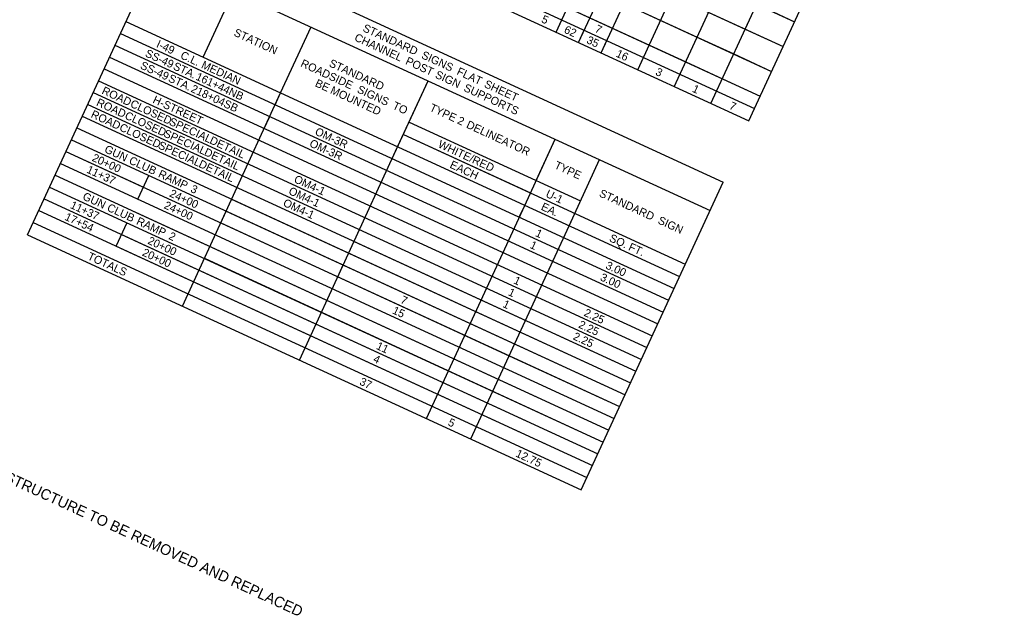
# Model space of a CAD drawing. Extents: x 627405 to 651306, y 367647 to 373471.
# Drawn here: x 650493 to 651042, y 372520 to 372856 of the extents above; entities that cross this region are included whole.
import ezdxf

# ---------------------------------------------------------------- set-up
doc = ezdxf.new("R2010")
doc.units = 0
doc.layers.add('Default', color=7, linetype='Continuous')
doc.layers.add('R_Dimension', color=7, linetype='Continuous')

msp = doc.modelspace()

# ---------------------------------------------------------------- linework, layer by layer
at = {"layer": 'Default'}
for p, q in [((650794.98, 372848.38), (650933.62, 373149.23)), ((650807.6, 372842.57), (650946.23, 373143.42)), ((650820.22, 372836.75), (650958.85, 373137.61)), ((650840.81, 372827.27), (650979.44, 373128.12)), ((650861.39, 372817.78), (651000.03, 373118.63)), ((650881.98, 372808.29), (651020.62, 373109.14)), ((650901.26, 372850.13), (651020.62, 373109.14)), ((650906.45, 372805.47), (651041.87, 373099.35)), ((650601.19, 373005.32), (650928.94, 372854.29)), ((650594.77, 372991.37), (650922.51, 372840.34)), ((650588.34, 372977.42), (650916.09, 372826.39)), ((650581.91, 372963.48), (650909.66, 372812.45)), ((650578.7, 372956.5), (650906.45, 372805.47)), ((650575.49, 372949.53), (650903.23, 372798.5)), ((650696.05, 372944.7), (650901.26, 372850.13)), ((650689.62, 372930.75), (650874.25, 372845.67)), ((650683.19, 372916.81), (650867.82, 372831.73)), ((650497.93, 372734.46), (650577.65, 372907.47)), ((650577.65, 372907.47), (650888.79, 372764.09)), ((650570.3, 372891.53), (650881.45, 372748.15)), ((650596.67, 372834.29), (650613.8, 372871.48)), ((650907.69, 372864.08), (650928.94, 372854.29)), ((650553.17, 372854.34), (650640.17, 372814.25)), ((650553.17, 372854.34), (650640.17, 372814.25)), ((650794.98, 372848.38), (650798.19, 372855.36)), ((650550.11, 372847.7), (650861.25, 372704.32)), ((650640.17, 372814.25), (650657.3, 372851.44)), ((650807.6, 372842.57), (650810.81, 372849.54)), ((650901.26, 372850.13), (650922.51, 372840.34)), ((650820.22, 372836.75), (650823.43, 372843.73)), ((650874.25, 372845.67), (650894.84, 372836.19)), ((650547.04, 372841.06), (650858.19, 372697.68)), ((650543.98, 372834.42), (650855.13, 372691.04)), ((650840.81, 372827.27), (650844.02, 372834.24)), ((650867.82, 372831.73), (650888.41, 372822.24)), ((650894.84, 372836.19), (650916.09, 372826.39)), ((650540.92, 372827.77), (650852.07, 372684.4)), ((650537.86, 372821.13), (650849.01, 372677.75)), ((650702.86, 372777.31), (650723.05, 372821.14)), ((650705.92, 372783.95), (650723.05, 372821.14)), ((650888.41, 372822.24), (650909.66, 372812.45)), ((650534.8, 372814.49), (650845.95, 372671.11)), ((650584.93, 372694.37), (650640.17, 372814.25)), ((650637.11, 372807.61), (650640.17, 372814.25)), ((650640.17, 372814.25), (650864.31, 372710.96)), ((650531.74, 372807.85), (650842.89, 372664.47)), ((650903.23, 372798.5), (650906.45, 372805.47)), ((650528.68, 372801.21), (650839.83, 372657.83)), ((650630.99, 372794.32), (650634.05, 372800.97)), ((650525.62, 372794.57), (650836.77, 372651.19)), ((650712.34, 372797.9), (650808.64, 372753.52)), ((650522.56, 372787.93), (650833.71, 372644.55)), ((650709.13, 372790.92), (650867.52, 372717.93)), ((650709.13, 372790.92), (650780.52, 372758.03)), ((650777.31, 372751.05), (650794.45, 372788.24)), ((650783.74, 372765), (650794.45, 372788.24)), ((650650.68, 372664.08), (650705.92, 372783.95)), ((650519.5, 372781.28), (650563, 372761.24)), ((650519.5, 372781.28), (650830.65, 372637.91)), ((650802.21, 372739.58), (650819.35, 372776.77)), ((650516.44, 372774.64), (650827.59, 372631.27)), ((650516.44, 372774.64), (650827.59, 372631.27)), ((650513.38, 372768), (650824.53, 372624.62)), ((650559.94, 372754.6), (650566.06, 372767.88)), ((650559.94, 372754.6), (650566.06, 372767.88)), ((650510.32, 372761.36), (650821.47, 372617.98)), ((650809.07, 372591.09), (650888.79, 372764.09)), ((650809.07, 372591.09), (650888.79, 372764.09)), ((650507.26, 372754.72), (650818.4, 372611.34)), ((650612.62, 372754.48), (650836.77, 372651.19)), ((650722.07, 372631.18), (650777.31, 372751.05)), ((650774.25, 372744.41), (650777.31, 372751.05)), ((650504.2, 372748.08), (650815.34, 372604.7)), ((650556.88, 372747.96), (650824.53, 372624.62)), ((650606.5, 372741.19), (650609.56, 372747.84)), ((650609.56, 372747.84), (650833.71, 372644.55)), ((650802.21, 372739.58), (650805.43, 372746.55)), ((650501.14, 372741.44), (650812.28, 372598.06)), ((650501.14, 372741.44), (650812.28, 372598.06)), ((650547.7, 372728.03), (650553.82, 372741.32)), ((650547.7, 372728.03), (650553.82, 372741.32)), ((650606.5, 372741.19), (650768.55, 372666.52)), ((650746.97, 372619.7), (650802.21, 372739.58)), ((650497.93, 372734.46), (650809.07, 372591.09)), ((650550.76, 372734.67), (650818.4, 372611.34)), ((650547.7, 372728.03), (650815.34, 372604.7)), ((650681.43, 372730.82), (650839.83, 372657.83)), ((650597.32, 372721.27), (650821.47, 372617.98)), ((650672.25, 372710.9), (650675.31, 372717.54)), ((650768.55, 372666.52), (650830.65, 372637.91))]:
    msp.add_line(p, q, dxfattribs=at)

# ---------------------------------------------------------------- texts
for s, p in [('5', (650786.29, 372854.14)), ('STATION', (650613.41, 372846.64)), ('STANDARD', (650685.89, 372849.17)), ('62', (650799.01, 372848.28)), ('7', (650816.35, 372848.74)), ('I-49', (650569.88, 372840.13)), ('CHANNEL', (650681.23, 372843.88)), ('35', (650811.65, 372842.45)), ('SS-49', (650563.62, 372834.97)), (' C.L.', (650581.91, 372834.59)), (' SIGNS', (650717.32, 372834.68)), ('16', (650828.2, 372834.82)), ('SS-49', (650560.87, 372828.18)), (' STA.', (650577.82, 372828.42)), (' MEDIAN', (650593.64, 372829.18)), ('ROADSIDE', (650650.99, 372829.33)), ('STANDARD', (650666.95, 372829.4)), (' POST', (650708.4, 372831.36)), (' SIGN', (650725.07, 372823.68)), (' FLAT', (650737.22, 372825.51)), ('3', (650850.39, 372824.6)), (' STA.', (650575.07, 372821.64)), (' 161+44NB', (650590.53, 372822.57)), ('BE', (650659.1, 372818.16)), (' SHEET', (650752.64, 372818.41)), ('ROAD', (650539.24, 372814)), (' 218+04SB', (650587.78, 372815.78)), (' MOUNTED', (650666.14, 372814.91)), (' SIGNS', (650681.22, 372815.4)), (' SUPPORTS', (650741.1, 372816.29)), ('1', (650871.05, 372815.08)), ('ROAD', (650536.18, 372807.36)), (' CLOSED', (650553.71, 372807.33)), ('H-STREET', (650567.87, 372808.85)), (' TO', (650701.12, 372806.23)), ('7', (650891.84, 372805.5)), ('ROAD', (650533.12, 372800.71)), ('TYPE', (650723.43, 372804.4)), (' CLOSED', (650550.65, 372800.69)), (' SPECIAL', (650575.53, 372797.27)), (' 2', (650737.52, 372797.91)), (' DELINEATOR', (650742.58, 372795.58)), (' CLOSED', (650547.59, 372794.04)), (' SPECIAL', (650572.47, 372790.63)), ('OM-3R', (650659.01, 372791.01)), (' DETAIL', (650598.3, 372786.78)), ('OM-3R', (650655.95, 372784.37)), ('WHITE/RED', (650728.22, 372783.88)), ('GUN', (650540.73, 372781.1)), (' SPECIAL', (650569.41, 372783.99)), (' DETAIL', (650595.24, 372780.14)), ('20+00', (650533.77, 372776.26)), (' CLUB', (650552.99, 372775.45)), (' DETAIL', (650592.17, 372773.5)), ('11+37', (650530.7, 372769.62)), (' RAMP', (650569.45, 372767.87)), ('EACH', (650734.81, 372772.38)), ('TYPE', (650793.56, 372772.09)), ('OM4-1', (650647.25, 372764.22)), ('24+00', (650577.27, 372756.21)), (' 3', (650587.61, 372759.5)), ('OM4-1', (650644.19, 372757.58)), ('U-1', (650788.73, 372755.99)), ('STANDARD', (650818.76, 372756.24)), ('GUN', (650528.44, 372754.56)), ('OM4-1', (650641.13, 372750.94)), ('11+37', (650521.52, 372749.7)), (' CLUB', (650540.7, 372748.91)), ('24+00', (650574.21, 372749.57)), ('EA.', (650786.09, 372748.75)), ('17+54', (650518.43, 372743.07)), (' RAMP', (650557.16, 372741.33)), (' SIGN', (650850.2, 372741.76)), ('20+00', (650565.03, 372729.65)), (' 2', (650575.32, 372732.96)), ('1', (650782.92, 372733.91)), ('SQ.', (650824.45, 372731.08)), ('1', (650779.86, 372727.27)), (' FT.', (650833.7, 372726.82)), ('TOTALS', (650531.23, 372720.87)), ('20+00', (650561.97, 372723)), ('3.00', (650822.39, 372715.72)), ('1', (650770.68, 372707.35)), ('3.00', (650819.33, 372709.08)), ('7', (650707.1, 372696.38)), ('1', (650767.62, 372700.7)), ('1', (650764.56, 372694.06)), ('15', (650702.56, 372690.43)), ('2.25', (650810.18, 372689.14)), ('2.25', (650807.12, 372682.5)), ('2.25', (650804.06, 372675.86)), ('11', (650693.46, 372670.47)), ('4', (650691.77, 372663.19)), ('37', (650684.07, 372650.44)), ('5', (650733.8, 372627.52)), ('12.75', (650771.85, 372609.99))]:
    msp.add_text(s, height=4.5, rotation=335.2593, dxfattribs=at).set_placement(p)
at = {"layer": 'R_Dimension'}
msp.add_text('** EXISTING SIGN AND STRUCTURE TO BE REMOVED AND REPLACED', height=6, rotation=335.2593, dxfattribs=at).set_placement((650403.5, 372633.5))

doc.saveas('drawing.dxf')
